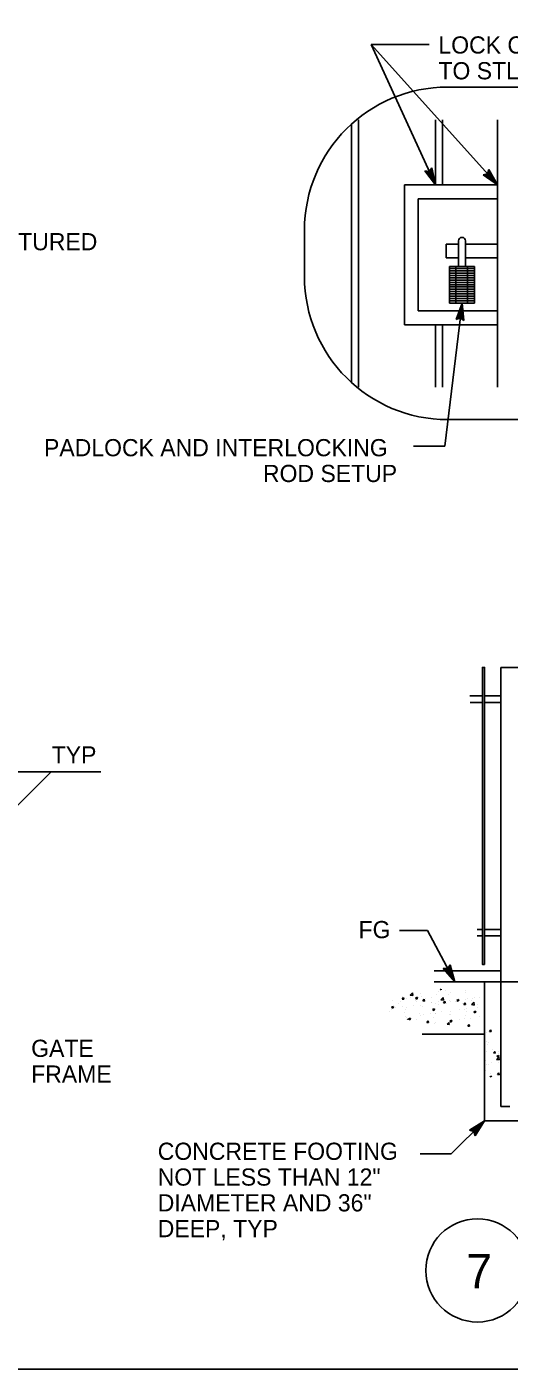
# Model space of a CAD drawing. Extents: x 6710407 to 6714861, y 1868090 to 1871317.
# Drawn here: x 6711990.6 to 6712158.9, y 1869155.1 to 1869623.6 of the extents above; entities that cross this region are included whole.
import ezdxf

# ---------------------------------------------------------------- set-up
doc = ezdxf.new("R2010")
doc.units = 0
for name, color, linetype in [('Erosion C (Lv35)', 7, 'Continuous'), ('G-MARK', 7, 'Continuous'), ('G-TEXT', 7, 'Continuous'), ('G-TTLB-VIEW', 7, 'Continuous'), ('Misc CnstDet(22)', 7, 'Continuous'), ('Nongeo Data(60)', 7, 'Continuous')]:
    doc.layers.add(name, color=color, linetype=linetype)

# ---------------------------------------------------------------- blocks, each defined once
blk = doc.blocks.new('SC8415')
at = {"layer": 'Erosion C (Lv35)'}
for p, q in [((-1.70955, 1.76614), (-1.70906, 1.76672)), ((-1.70943, 1.76711), (-1.70943, 1.76711)), ((-1.70894, 1.76609), (-1.70906, 1.76672)), ((-1.70791, 1.76649), (-1.70791, 1.76649)), ((-1.70689, 1.76745), (-1.70689, 1.76745)), ((-1.70672, 1.76656), (-1.70672, 1.76656)), ((-1.70669, 1.76754), (-1.7059, 1.76836)), ((-1.70669, 1.76754), (-1.70579, 1.7674)), ((-1.70579, 1.7674), (-1.7059, 1.76836)), ((-1.70484, 1.76651), (-1.70412, 1.76679)), ((-1.70484, 1.76651), (-1.70433, 1.76617)), ((-1.70433, 1.76617), (-1.70412, 1.76679)), ((-1.70304, 1.76795), (-1.70304, 1.76795)), ((-1.70278, 1.76714), (-1.70278, 1.76714)), ((-1.7013, 1.76633), (-1.7013, 1.76633)), ((-1.69901, 1.76659), (-1.69901, 1.76659)), ((-1.6975, 1.7679), (-1.6975, 1.7679)), ((-1.69662, 1.7688), (-1.69662, 1.7688)), ((-1.69606, 1.76963), (-1.69579, 1.76945)), ((-1.69585, 1.76586), (-1.69506, 1.76668)), ((-1.69579, 1.76945), (-1.69573, 1.76963)), ((-1.69494, 1.76572), (-1.69506, 1.76668)), ((-1.69408, 1.76913), (-1.69408, 1.76913)), ((-1.69309, 1.7676), (-1.69309, 1.7676)), ((-1.69228, 1.76861), (-1.69228, 1.76861)), ((-1.68716, 1.76862), (-1.68716, 1.76862)), ((-1.68715, 1.76926), (-1.68715, 1.76926)), ((-1.68649, 1.76648), (-1.68649, 1.76648)), ((-1.68473, 1.76639), (-1.68473, 1.76639)), ((-1.68394, 1.76681), (-1.68394, 1.76681)), ((-1.682, 1.76664), (-1.682, 1.76664)), ((-1.71417, 1.76163), (-1.71417, 1.76163)), ((-1.71337, 1.76324), (-1.71266, 1.76351)), ((-1.71337, 1.76324), (-1.71287, 1.7629)), ((-1.71325, 1.76239), (-1.71325, 1.76239)), ((-1.71312, 1.76577), (-1.71312, 1.76577)), ((-1.71287, 1.7629), (-1.71266, 1.76351)), ((-1.7121, 1.7631), (-1.7121, 1.7631)), ((-1.71086, 1.76455), (-1.71086, 1.76455)), ((-1.71, 1.76543), (-1.71, 1.76543)), ((-1.70956, 1.76344), (-1.70956, 1.76344)), ((-1.70955, 1.76614), (-1.70894, 1.76608)), ((-1.70843, 1.76232), (-1.70843, 1.76232)), ((-1.70803, 1.7631), (-1.70803, 1.7631)), ((-1.70571, 1.76395), (-1.70571, 1.76395)), ((-1.70494, 1.76557), (-1.70494, 1.76557)), ((-1.70458, 1.7652), (-1.70458, 1.7652)), ((-1.7029, 1.76375), (-1.7029, 1.76375)), ((-1.7025, 1.76334), (-1.7025, 1.76334)), ((-1.70226, 1.7655), (-1.70177, 1.76608)), ((-1.70226, 1.7655), (-1.70165, 1.76545)), ((-1.70165, 1.76545), (-1.70177, 1.76609)), ((-1.6993, 1.76479), (-1.6993, 1.76479)), ((-1.69916, 1.76497), (-1.69916, 1.76497)), ((-1.69877, 1.76242), (-1.69806, 1.7627)), ((-1.69877, 1.76242), (-1.69827, 1.76208)), ((-1.69826, 1.76208), (-1.69806, 1.7627)), ((-1.69762, 1.76452), (-1.69762, 1.76452)), ((-1.69675, 1.76513), (-1.69675, 1.76513)), ((-1.69658, 1.76435), (-1.69658, 1.76435)), ((-1.69588, 1.7661), (-1.69588, 1.7661)), ((-1.69585, 1.76586), (-1.69494, 1.76572)), ((-1.69558, 1.76162), (-1.69558, 1.76162)), ((-1.69497, 1.76486), (-1.69449, 1.76545)), ((-1.69497, 1.76486), (-1.69437, 1.76481)), ((-1.69437, 1.76481), (-1.69448, 1.76545)), ((-1.69373, 1.76474), (-1.69373, 1.76474)), ((-1.6929, 1.76563), (-1.6929, 1.76563)), ((-1.69253, 1.76185), (-1.69253, 1.76185)), ((-1.69241, 1.76523), (-1.69241, 1.76523)), ((-1.69065, 1.76537), (-1.69065, 1.76537)), ((-1.69045, 1.76587), (-1.69045, 1.76587)), ((-1.69023, 1.7657), (-1.68952, 1.76597)), ((-1.69023, 1.7657), (-1.68973, 1.76536)), ((-1.68973, 1.76536), (-1.68952, 1.76597)), ((-1.68916, 1.76247), (-1.68916, 1.76247)), ((-1.68831, 1.76451), (-1.68831, 1.76451)), ((-1.68769, 1.76423), (-1.6872, 1.76481)), ((-1.68769, 1.76423), (-1.68708, 1.76417)), ((-1.6874, 1.7625), (-1.6874, 1.7625)), ((-1.68727, 1.76588), (-1.68727, 1.76588)), ((-1.68708, 1.76417), (-1.6872, 1.76481)), ((-1.68677, 1.76182), (-1.68677, 1.76182)), ((-1.68662, 1.7628), (-1.68662, 1.7628)), ((-1.68503, 1.76565), (-1.68503, 1.76565)), ((-1.685, 1.76418), (-1.68421, 1.765)), ((-1.685, 1.76418), (-1.6841, 1.76404)), ((-1.6841, 1.76404), (-1.68421, 1.765)), ((-1.68417, 1.76161), (-1.68346, 1.76188)), ((-1.68417, 1.76161), (-1.68366, 1.76127)), ((-1.68366, 1.76127), (-1.68346, 1.76188)), ((-1.68289, 1.76428), (-1.68289, 1.76428)), ((-1.68277, 1.76331), (-1.68277, 1.76331)), ((-1.70874, 1.7614), (-1.70874, 1.7614)), ((-1.70839, 1.75994), (-1.70839, 1.75994)), ((-1.70815, 1.75972), (-1.70815, 1.75972)), ((-1.70775, 1.75896), (-1.70765, 1.75908)), ((-1.70762, 1.7589), (-1.70765, 1.75908)), ((-1.70731, 1.75915), (-1.7066, 1.75942)), ((-1.70731, 1.75915), (-1.7068, 1.75881)), ((-1.7068, 1.75881), (-1.7066, 1.75942)), ((-1.70455, 1.75876), (-1.70455, 1.75876)), ((-1.70332, 1.76117), (-1.70332, 1.76117)), ((-1.70302, 1.76037), (-1.70302, 1.76037)), ((-1.70197, 1.76078), (-1.70197, 1.76078)), ((-1.70085, 1.75786), (-1.70036, 1.75844)), ((-1.70085, 1.75786), (-1.70025, 1.7578)), ((-1.70024, 1.75781), (-1.70036, 1.75844)), ((-1.69943, 1.76112), (-1.69943, 1.76112)), ((-1.69862, 1.75978), (-1.69862, 1.75978)), ((-1.69825, 1.75762), (-1.69825, 1.75762)), ((-1.6979, 1.76094), (-1.6979, 1.76094)), ((-1.69787, 1.75775), (-1.69787, 1.75775)), ((-1.69775, 1.76113), (-1.69775, 1.76113)), ((-1.69357, 1.75722), (-1.69308, 1.7578)), ((-1.69357, 1.75722), (-1.69296, 1.75717)), ((-1.69296, 1.75717), (-1.69307, 1.75781)), ((-1.69271, 1.75833), (-1.692, 1.75861)), ((-1.69271, 1.75833), (-1.6922, 1.75799)), ((-1.6927, 1.7608), (-1.6927, 1.7608)), ((-1.69265, 1.75847), (-1.69265, 1.75847)), ((-1.69247, 1.76071), (-1.69247, 1.76071)), ((-1.6922, 1.75799), (-1.69199, 1.75861)), ((-1.69183, 1.75846), (-1.69183, 1.75846)), ((-1.68929, 1.7588), (-1.68929, 1.7588)), ((-1.68752, 1.75912), (-1.68752, 1.75912)), ((-1.68705, 1.76048), (-1.68705, 1.76048)), ((-1.68628, 1.75658), (-1.68579, 1.75717)), ((-1.68567, 1.75653), (-1.68579, 1.75717)), ((-1.68544, 1.7593), (-1.68544, 1.7593)), ((-1.68224, 1.75988), (-1.68224, 1.75988)), ((-1.68628, 1.75658), (-1.68567, 1.75653))]:
    blk.add_line(p, q, dxfattribs=at)

msp = doc.modelspace()

# ---------------------------------------------------------------- linework, layer by layer
at = {"layer": 'G-MARK'}
for p, q in [((6712133.17, 1869568.45), (6712110.66, 1869617.43)), ((6712110.66, 1869617.43), (6712154.82, 1869568.45)), ((6712110.66, 1869617.43), (6712130.94, 1869617.43)), ((6712142.41, 1869527.24), (6712136.38, 1869477.27)), ((6712136.38, 1869477.27), (6712125.48, 1869477.27)), ((6711957.53, 1869363.61), (6712016.38, 1869363.61)), ((6711987.05, 1869351.61), (6711999.05, 1869363.61)), ((6712130.35, 1869308.24), (6712120.56, 1869308.24)), ((6712139.87, 1869290.29), (6712130.35, 1869308.24)), ((6712138.59, 1869230.19), (6712150.29, 1869241.71)), ((6712127.79, 1869230.19), (6712138.59, 1869230.19))]:
    msp.add_line(p, q, dxfattribs=at)
at = {"layer": 'G-TEXT'}
for p, q in [((6712133.17, 1869568.45), (6712129.45, 1869573.35)), ((6712129.45, 1869573.35), (6712129.45, 1869573.35)), ((6712129.45, 1869573.35), (6712130.99, 1869573.18)), ((6712132.58, 1869569.71), (6712129.88, 1869573.29)), ((6712132.01, 1869570.96), (6712130.27, 1869573.27)), ((6712131.44, 1869572.22), (6712130.69, 1869573.21)), ((6712130.99, 1869573.18), (6712131.88, 1869574.46)), ((6712131.17, 1869573.45), (6712131.44, 1869572.22)), ((6712131.42, 1869573.76), (6712132.01, 1869570.96)), ((6712131.65, 1869574.12), (6712132.59, 1869569.71)), ((6712131.88, 1869574.46), (6712131.88, 1869574.46)), ((6712131.88, 1869574.46), (6712133.17, 1869568.45)), ((6712149.82, 1869572.02), (6712151.34, 1869572.31)), ((6712154.82, 1869568.45), (6712149.82, 1869572.02)), ((6712149.82, 1869572.02), (6712149.82, 1869572.02)), ((6712153.89, 1869569.48), (6712150.24, 1869572.08)), ((6712152.97, 1869570.51), (6712150.62, 1869572.18)), ((6712152.05, 1869571.53), (6712151.04, 1869572.25)), ((6712151.34, 1869572.31), (6712151.8, 1869573.81)), ((6712151.43, 1869572.63), (6712152.05, 1869571.53)), ((6712151.57, 1869572.99), (6712152.97, 1869570.51)), ((6712151.68, 1869573.41), (6712153.9, 1869569.48)), ((6712151.8, 1869573.81), (6712151.8, 1869573.81)), ((6712151.8, 1869573.81), (6712154.82, 1869568.45)), ((6712133.17, 1869568.45), (6712133.17, 1869568.45)), ((6712154.82, 1869568.45), (6712154.82, 1869568.45)), ((6712142.41, 1869527.24), (6712140.37, 1869521.44)), ((6712142.24, 1869525.86), (6712140.76, 1869521.63)), ((6712142.7, 1869521.38), (6712142.25, 1869525.87)), ((6712143.02, 1869521.12), (6712142.41, 1869527.24)), ((6712142.41, 1869527.24), (6712142.41, 1869527.24)), ((6712140.37, 1869521.44), (6712141.79, 1869522.08)), ((6712140.37, 1869521.44), (6712140.37, 1869521.44)), ((6712142.08, 1869524.49), (6712141.12, 1869521.76)), ((6712141.92, 1869523.12), (6712141.51, 1869521.95)), ((6712141.79, 1869522.08), (6712143.02, 1869521.12)), ((6712142.04, 1869521.87), (6712141.92, 1869523.12)), ((6712142.37, 1869521.65), (6712142.08, 1869524.49)), ((6712143.02, 1869521.12), (6712143.02, 1869521.12)), ((6712138.23, 1869296.21), (6712137.43, 1869294.88)), ((6712138.57, 1869292.72), (6712137.8, 1869295.51)), ((6712139.22, 1869291.52), (6712138.03, 1869295.83)), ((6712139.87, 1869290.28), (6712138.23, 1869296.21)), ((6712138.23, 1869296.21), (6712138.23, 1869296.21)), ((6712137.43, 1869294.88), (6712135.87, 1869294.96)), ((6712135.87, 1869294.96), (6712135.87, 1869294.96)), ((6712135.87, 1869294.96), (6712139.87, 1869290.28)), ((6712136.29, 1869294.93), (6712139.22, 1869291.5)), ((6712136.72, 1869294.9), (6712138.57, 1869292.72)), ((6712137.11, 1869294.9), (6712137.92, 1869293.94)), ((6712137.92, 1869293.94), (6712137.6, 1869295.14)), ((6712139.87, 1869290.28), (6712139.87, 1869290.28)), ((6712145.07, 1869238.45), (6712150.29, 1869241.71)), ((6712145.48, 1869238.35), (6712149.31, 1869240.74)), ((6712145.9, 1869238.26), (6712148.32, 1869239.77)), ((6712148.32, 1869239.77), (6712146.75, 1869237.34)), ((6712149.3, 1869240.73), (6712146.86, 1869236.97)), ((6712150.29, 1869241.71), (6712146.95, 1869236.55)), ((6712150.29, 1869241.71), (6712150.29, 1869241.71)), ((6712146.58, 1869238.06), (6712145.07, 1869238.45)), ((6712145.07, 1869238.45), (6712145.07, 1869238.45)), ((6712146.27, 1869238.14), (6712147.33, 1869238.8)), ((6712146.95, 1869236.55), (6712146.58, 1869238.06)), ((6712147.33, 1869238.8), (6712146.66, 1869237.76)), ((6712146.95, 1869236.55), (6712146.95, 1869236.55))]:
    msp.add_line(p, q, dxfattribs=at)
at = {"layer": 'G-TTLB-VIEW'}
msp.add_lwpolyline([(6711433.78, 1870605.06), (6713227.53, 1870605.06), (6713227.53, 1869155.06), (6711433.78, 1869155.06)], close=True, dxfattribs=at)
at = {"layer": 'Misc CnstDet(22)'}
for p, q in [((6712137.42, 1869602.64), (6712201.42, 1869602.64)), ((6712154.82, 1869591.15), (6712154.82, 1869519.68)), ((6712122.34, 1869519.68), (6712122.34, 1869568.45)), ((6712122.34, 1869568.45), (6712154.82, 1869568.45)), ((6712127.14, 1869524.48), (6712127.14, 1869563.65)), ((6712127.14, 1869563.65), (6712154.82, 1869563.65)), ((6712087.42, 1869536.54), (6712087.42, 1869552.64)), ((6712141.21, 1869548.96), (6712141.21, 1869540.04)), ((6712143.61, 1869548.96), (6712143.61, 1869540.04)), ((6712136.9, 1869542.96), (6712136.9, 1869547.76)), ((6712141.21, 1869547.76), (6712136.9, 1869547.76)), ((6712154.82, 1869547.76), (6712143.61, 1869547.76)), ((6712141.21, 1869542.96), (6712136.9, 1869542.96)), ((6712141.21, 1869540.04), (6712138.01, 1869540.04)), ((6712138.01, 1869540.04), (6712138.01, 1869527.24)), ((6712146.81, 1869539.24), (6712138.01, 1869539.24)), ((6712140.3, 1869540.04), (6712140.3, 1869527.24)), ((6712141.21, 1869540.04), (6712143.61, 1869540.04)), ((6712154.82, 1869542.96), (6712143.61, 1869542.96)), ((6712143.61, 1869540.04), (6712146.81, 1869540.04)), ((6712144.35, 1869540.04), (6712144.35, 1869527.24)), ((6712146.81, 1869540.04), (6712146.81, 1869527.24)), ((6712146.81, 1869538.44), (6712138.01, 1869538.44)), ((6712146.81, 1869537.64), (6712138.01, 1869537.64)), ((6712146.81, 1869536.84), (6712138.01, 1869536.84)), ((6712146.81, 1869536.04), (6712138.01, 1869536.04)), ((6712146.81, 1869535.24), (6712138.01, 1869535.24)), ((6712146.81, 1869534.44), (6712138.01, 1869534.44)), ((6712146.81, 1869533.64), (6712138.01, 1869533.64)), ((6712146.81, 1869532.84), (6712138.01, 1869532.84)), ((6712146.81, 1869532.04), (6712138.01, 1869532.04)), ((6712146.81, 1869531.24), (6712138.01, 1869531.24)), ((6712146.81, 1869530.44), (6712138.01, 1869530.44)), ((6712146.81, 1869529.64), (6712138.01, 1869529.64)), ((6712146.81, 1869528.84), (6712138.01, 1869528.84)), ((6712146.81, 1869528.04), (6712138.01, 1869528.04)), ((6712138.01, 1869527.24), (6712146.81, 1869527.24)), ((6712154.82, 1869524.48), (6712127.14, 1869524.48)), ((6712154.82, 1869519.68), (6712122.34, 1869519.68)), ((6712154.82, 1869519.68), (6712154.82, 1869497.85)), ((6712201.42, 1869486.54), (6712137.42, 1869486.54))]:
    msp.add_line(p, q, dxfattribs=at)
for points in [[(6712106.34, 1869591.15), (6712106.34, 1869497.85)], [(6712133.17, 1869568.45), (6712133.17, 1869591.15)], [(6712135.6, 1869591.15), (6712135.6, 1869568.45)], [(6712103.9, 1869499.43), (6712103.9, 1869589.74)], [(6712133.17, 1869497.85), (6712133.17, 1869519.68)], [(6712135.6, 1869519.68), (6712135.6, 1869497.85)]]:
    msp.add_lwpolyline(points, dxfattribs=at)
for centre, radius, start, end in [((6712137.42, 1869552.64), 50, 90, 180), ((6712142.41, 1869548.96), 1.2, 0.004, 180), ((6712142.41, 1869548.96), 1.2, 359.996, 0), ((6712137.42, 1869536.54), 50, 180, 270)]:
    msp.add_arc(centre, radius, start, end, dxfattribs=at)
at = {"layer": 'Nongeo Data(60)'}
for p, q in [((6712155.91, 1869400.01), (6712155.91, 1869340.58)), ((6712155.91, 1869400.01), (6712162.2, 1869400.01)), ((6712158.67, 1869400.01), (6712158.67, 1869400.01)), ((6712149.53, 1869390.11), (6712145.12, 1869390.11)), ((6712150.29, 1869390.11), (6712155.91, 1869390.11)), ((6712155.91, 1869390.11), (6712153.78, 1869390.11)), ((6712149.53, 1869387.82), (6712145.21, 1869387.82)), ((6712150.29, 1869387.82), (6712155.91, 1869387.82)), ((6712155.91, 1869387.82), (6712153.78, 1869387.82)), ((6712155.91, 1869340.58), (6712155.91, 1869246.7)), ((6712150.29, 1869296.38), (6712150.29, 1869317.72)), ((6712149.53, 1869308.57), (6712147.7, 1869308.57)), ((6712149.53, 1869306.29), (6712147.7, 1869306.29)), ((6712150.29, 1869308.57), (6712155.91, 1869308.57)), ((6712150.29, 1869306.29), (6712155.91, 1869306.29)), ((6712132.64, 1869294.11), (6712155.91, 1869294.11)), ((6712132.64, 1869290.29), (6712438.11, 1869290.29)), ((6712150.29, 1869290.29), (6712150.29, 1869253.71)), ((6712150.29, 1869272), (6712128.52, 1869272)), ((6712150.41, 1869272.46), (6712150.41, 1869272.46)), ((6712151.13, 1869272.76), (6712151.13, 1869272.76)), ((6712152.03, 1869272.96), (6712152.51, 1869273.53)), ((6712152.03, 1869272.96), (6712152.62, 1869272.9)), ((6712152.63, 1869272.9), (6712152.51, 1869273.53)), ((6712151.01, 1869269.43), (6712151.01, 1869269.43)), ((6712151.29, 1869268.27), (6712151.29, 1869268.27)), ((6712151.56, 1869269.01), (6712151.56, 1869269.01)), ((6712150.77, 1869262.77), (6712150.77, 1869262.77)), ((6712150.89, 1869266.1), (6712150.89, 1869266.1)), ((6712153.01, 1869266.61), (6712153.01, 1869266.61)), ((6712153.41, 1869265.43), (6712153.9, 1869266.01)), ((6712153.41, 1869265.43), (6712154.01, 1869265.38)), ((6712153.69, 1869266.08), (6712153.69, 1869266.08)), ((6712154.01, 1869265.38), (6712153.9, 1869266.01)), ((6712154.46, 1869263.17), (6712155.24, 1869263.99)), ((6712154.46, 1869263.17), (6712155.35, 1869263.04)), ((6712154.6, 1869264.34), (6712155.3, 1869264.61)), ((6712154.6, 1869264.34), (6712155.09, 1869264.01)), ((6712155.1, 1869264.01), (6712155.3, 1869264.61)), ((6712155.12, 1869265.27), (6712155.12, 1869265.27)), ((6712155.35, 1869263.04), (6712155.24, 1869263.99)), ((6712155.25, 1869265.9), (6712155.25, 1869265.9)), ((6712150.65, 1869259.44), (6712150.65, 1869259.44)), ((6712151.02, 1869261.53), (6712151.02, 1869261.53)), ((6712151.67, 1869261.58), (6712151.67, 1869261.58)), ((6712152.49, 1869258.34), (6712152.49, 1869258.34)), ((6712152.62, 1869261.96), (6712152.62, 1869261.96)), ((6712154.8, 1869257.91), (6712155.28, 1869258.49)), ((6712154.8, 1869257.91), (6712155.4, 1869257.86)), ((6712155.12, 1869262.28), (6712155.12, 1869262.28)), ((6712155.4, 1869257.86), (6712155.29, 1869258.49)), ((6712150.29, 1869253.71), (6712150.29, 1869241.71)), ((6712152.16, 1869257.09), (6712152.86, 1869257.36)), ((6712155.91, 1869246.7), (6712159.05, 1869246.7)), ((6712167.82, 1869241.71), (6712150.29, 1869241.71))]:
    msp.add_line(p, q, dxfattribs=at)
msp.add_lwpolyline([(6712150.29, 1869296.38), (6712149.53, 1869296.38), (6712149.53, 1869400.01), (6712150.29, 1869400.01)], close=True, dxfattribs=at)
msp.add_circle((6712147.79, 1869189.52), 18, dxfattribs=at)

# ---------------------------------------------------------------- block references
at = {"layer": 'Nongeo Data(60)', "xscale": 984.251968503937, "yscale": 984.251968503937}
msp.add_blockref('SC8415', (6713804.18, 1867545.92), dxfattribs=at)

# ---------------------------------------------------------------- texts
at = {"layer": 'Misc CnstDet(22)'}
for s, p in [('TYP', (6711999.23, 1869366.49)), ('GATE', (6711992.07, 1869264.07)), ('FRAME', (6711992.07, 1869255.07))]:
    msp.add_text(s, height=6, dxfattribs=at).set_placement(p)
at = {"layer": 'Nongeo Data(60)'}
for s, height, p in [('LOCK CUT-OUT WELDED', 6, (6712134.18, 1869614.32)), ('TO STL FENCE, TYP', 6, (6712134.18, 1869605.32)), ('AND FENCE SHALL BE MANUFACTURED', 6, (6711858.68, 1869545.65)), ('FG', 6, (6712106.31, 1869305.51)), ('CONCRETE FOOTING', 6, (6712036.23, 1869228.13)), ('NOT LESS THAN 12"', 6, (6712036.23, 1869219.13)), ('DIAMETER AND 36"', 6, (6712036.23, 1869210.13)), ('DEEP, TYP', 6, (6712036.23, 1869201.13)), ('7', 12, (6712143.95, 1869183.25))]:
    msp.add_text(s, height=height, dxfattribs=at).set_placement(p)
for s, p in [('PADLOCK AND INTERLOCKING', (6711996.55, 1869473.74)), ('ROD SETUP', (6712072.95, 1869464.74))]:
    msp.add_text(s, height=6, rotation=360, dxfattribs=at).set_placement(p)

doc.saveas('drawing.dxf')
